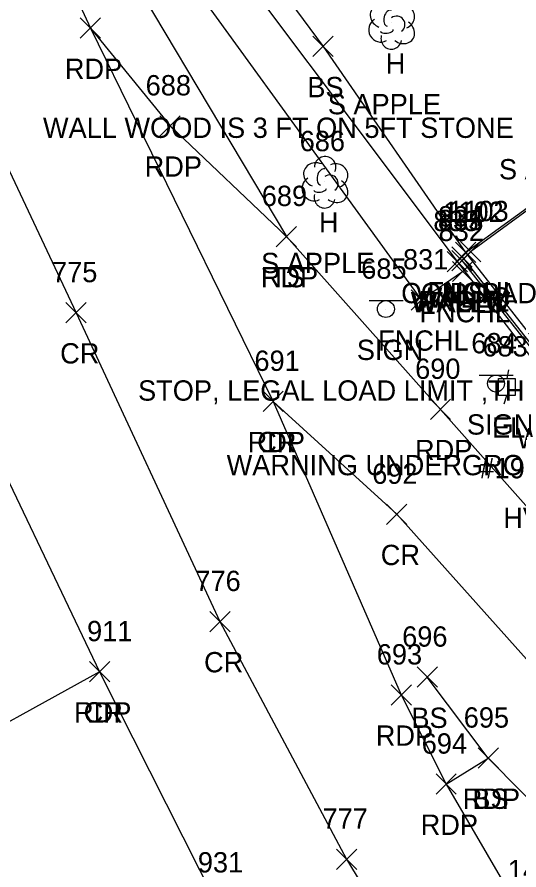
# Model space of a CAD drawing. Extents: x 1647133 to 1649138, y 411736 to 414924.
# Drawn here: x 1648639.6 to 1648689, y 412109.7 to 412193.6 of the extents above; entities that cross this region are included whole.
import ezdxf

# ---------------------------------------------------------------- set-up
doc = ezdxf.new("R2010")
doc.units = 0
for name, color, linetype in [('C_A', 7, 'Continuous'), ('L_A', 7, 'Continuous'), ('L_C', 7, 'Continuous'), ('L_I', 7, 'Continuous'), ('L_TIC', 7, 'Continuous'), ('LELB', 7, 'Continuous'), ('LFNC', 7, 'Continuous'), ('LS', 7, 'Continuous'), ('LTD', 7, 'Continuous'), ('LW', 7, 'Continuous'), ('P_A', 7, 'Continuous'), ('P_I', 7, 'Continuous'), ('P_TIC', 7, 'Continuous'), ('PET', 7, 'Continuous'), ('PRC', 7, 'Continuous'), ('R_I', 7, 'Continuous'), ('S_A', 7, 'Continuous'), ('S_C', 7, 'Continuous'), ('S_I', 7, 'Continuous'), ('SSGN', 7, 'Continuous'), ('U_A', 7, 'Continuous'), ('U_C', 7, 'Continuous'), ('U_I', 7, 'Continuous'), ('UEPT', 7, 'Continuous')]:
    doc.layers.add(name, color=color, linetype=linetype)

msp = doc.modelspace()

# ---------------------------------------------------------------- linework, layer by layer
at = {"layer": 'L_TIC'}
for points in [[(1648668.737, 412189.746), (1648670.737, 412191.746)], [(1648670.737, 412189.746), (1648668.737, 412191.746)], [(1648665.114, 412171.04), (1648667.114, 412173.04)], [(1648667.114, 412171.04), (1648665.114, 412173.04)], [(1648682.426, 412169.034), (1648684.426, 412171.034)], [(1648684.426, 412169.034), (1648682.426, 412171.034)], [(1648682.773, 412169.473), (1648684.773, 412171.473)], [(1648684.773, 412169.473), (1648682.773, 412171.473)], [(1648682.773, 412169.473), (1648684.773, 412171.473)], [(1648684.773, 412169.473), (1648682.773, 412171.473)], [(1648683.265, 412169.553), (1648685.265, 412171.553)], [(1648685.265, 412169.553), (1648683.265, 412171.553)], [(1648681.946, 412168.571), (1648683.946, 412170.571)], [(1648683.946, 412168.571), (1648681.946, 412170.571)], [(1648681.946, 412168.571), (1648683.946, 412170.571)], [(1648683.946, 412168.571), (1648681.946, 412170.571)], [(1648681.946, 412168.571), (1648683.946, 412170.571)], [(1648683.946, 412168.571), (1648681.946, 412170.571)], [(1648682.402, 412168.663), (1648684.402, 412170.663)], [(1648684.402, 412168.663), (1648682.402, 412170.663)], [(1648682.471, 412167.596), (1648684.471, 412169.596)], [(1648684.471, 412167.596), (1648682.471, 412169.596)], [(1648678.397, 412164.798), (1648680.397, 412166.798)], [(1648680.397, 412164.798), (1648678.397, 412166.798)], [(1648678.987, 412127.668), (1648680.987, 412129.668)], [(1648680.987, 412127.668), (1648678.987, 412129.668)], [(1648684.993, 412119.699), (1648686.993, 412121.699)], [(1648686.993, 412119.699), (1648684.993, 412121.699)]]:
    msp.add_lwpolyline(points, dxfattribs=at)
at = {"layer": 'LELB'}
for points in [[(1648569.547, 412372.007), (1648582.324, 412342.107), (1648598.266, 412308.648), (1648609.531, 412282.347), (1648621.029, 412259.099), (1648624.781, 412251.326), (1648635.367, 412226.993), (1648645.42, 412206.793), (1648666.114, 412172.04)], [(1648623.835, 412258.098), (1648637.368, 412228.397), (1648652.141, 412210.937), (1648646.596, 412221.306), (1648628.763, 412254.382), (1648641.62, 412261.648), (1648650.774, 412266.813), (1648653.575, 412263.089), (1648676.806, 412228.616), (1648679.956, 412223.635), (1648670.57, 412217.924), (1648655.389, 412210.124), (1648669.737, 412190.746), (1648683.773, 412170.473), (1648710.631, 412136.174)], [(1648685.993, 412120.699), (1648679.987, 412128.668)]]:
    msp.add_lwpolyline(points, dxfattribs=at)
at = {"layer": 'LFNC'}
for points in [[(1648652.618, 412210.345), (1648648.634, 412208.217), (1648679.397, 412165.798), (1648683.471, 412168.596)], [(1648684.265, 412170.553), (1648704.391, 412185.254), (1648720.455, 412164.525), (1648739.792, 412139.413), (1648738.276, 412138.056), (1648736.265, 412136.349), (1648725.233, 412127.52), (1648716.272, 412129.583)], [(1648683.402, 412169.663), (1648709.699, 412136.366)]]:
    msp.add_lwpolyline(points, dxfattribs=at)
at = {"layer": 'LS'}
msp.add_lwpolyline([(1648683.773, 412170.473), (1648704.589, 412185.571), (1648720.677, 412164.751), (1648740.213, 412139.354), (1648738.365, 412137.966), (1648738.276, 412138.056)], dxfattribs=at)
at = {"layer": 'LTD'}
for p, q in [((1648676.464, 412193.07), (1648676.464, 412193.07)), ((1648676.464, 412193.07), (1648676.464, 412193.07)), ((1648669.894, 412177.436), (1648669.894, 412177.436)), ((1648669.894, 412177.436), (1648669.894, 412177.436))]:
    msp.add_line(p, q, dxfattribs=at)
msp.add_arc((1648669.941, 412178.87), 1.047, 335.52715, 180.95627, dxfattribs=at)
for centre, major_axis, ratio, start_param, end_param in [((1648675.672, 412193.737), (1.21, -0.512), 0.895232, 1.570796, 4.712389), ((1648676.255, 412193.529), (-0.208, -0.792), 0.645439, 3.141593, 6.283185), ((1648677.505, 412193.654), (-1.141, -0.483), 0.949671, 1.570796, 4.712389), ((1648676.964, 412192.904), (-0.5, 0.667), 0.989748, 3.141593, 6.283185), ((1648675.381, 412192.362), (0.584, -1.042), 0.959034, 3.141593, 6.283185), ((1648677.464, 412192.237), (-1.09, 0.792), 0.841452, 1.570796, 4.712389), ((1648676.464, 412191.57), (0.265, 1.061), 0.942809, 1.570796, 4.712389), ((1648676.006, 412192.32), (-0.625, -0.083), 0.423636, 0, 3.141593), ((1648669.103, 412178.102), (1.21, -0.512), 0.895232, 1.570796, 4.712389), ((1648670.936, 412178.019), (-1.141, -0.483), 0.949671, 1.570796, 4.712389), ((1648669.686, 412177.894), (-0.208, -0.792), 0.645439, 3.141593, 6.283185), ((1648668.811, 412176.727), (0.584, -1.042), 0.959034, 3.141593, 6.283185), ((1648670.394, 412177.269), (-0.5, 0.667), 0.989748, 3.141593, 6.283185), ((1648670.895, 412176.602), (-1.09, 0.792), 0.841452, 1.570796, 4.712389), ((1648669.436, 412176.685), (-0.625, -0.083), 0.423636, 0, 3.141593), ((1648669.895, 412175.936), (0.265, 1.061), 0.942809, 1.570796, 4.712389)]:
    msp.add_ellipse(centre, major_axis=major_axis, ratio=ratio, start_param=start_param, end_param=end_param, dxfattribs=at)
at = {"layer": 'LW'}
for points in [[(1648653.627, 412208.663), (1648682.946, 412169.571)], [(1648682.946, 412169.571), (1648683.426, 412170.034), (1648710.056, 412136.22)], [(1648682.946, 412169.571), (1648693.247, 412156.182), (1648709.59, 412135.839), (1648710.056, 412136.22)]]:
    msp.add_lwpolyline(points, dxfattribs=at)
at = {"layer": 'P_TIC'}
for points in [[(1648645.814, 412191.55), (1648647.814, 412193.55)], [(1648647.814, 412191.55), (1648645.814, 412193.55)], [(1648645.814, 412191.55), (1648647.814, 412193.55)], [(1648647.814, 412191.55), (1648645.814, 412193.55)], [(1648653.671, 412181.929), (1648655.671, 412183.929)], [(1648655.671, 412181.929), (1648653.671, 412183.929)], [(1648665.114, 412171.04), (1648667.114, 412173.04)], [(1648667.114, 412171.04), (1648665.114, 412173.04)], [(1648644.407, 412163.541), (1648646.407, 412165.541)], [(1648646.407, 412163.541), (1648644.407, 412165.541)], [(1648663.816, 412154.812), (1648665.816, 412156.812)], [(1648665.816, 412154.812), (1648663.816, 412156.812)], [(1648663.816, 412154.812), (1648665.816, 412156.812)], [(1648665.816, 412154.812), (1648663.816, 412156.812)], [(1648680.295, 412154.026), (1648682.295, 412156.026)], [(1648682.295, 412154.026), (1648680.295, 412156.026)], [(1648675.979, 412143.697), (1648677.979, 412145.697)], [(1648677.979, 412143.697), (1648675.979, 412145.697)], [(1648658.578, 412133.14), (1648660.578, 412135.14)], [(1648660.578, 412133.14), (1648658.578, 412135.14)], [(1648646.722, 412128.202), (1648648.722, 412130.202)], [(1648648.722, 412128.202), (1648646.722, 412130.202)], [(1648646.722, 412128.202), (1648648.722, 412130.202)], [(1648648.722, 412128.202), (1648646.722, 412130.202)], [(1648676.431, 412125.914), (1648678.431, 412127.914)], [(1648678.431, 412125.914), (1648676.431, 412127.914)], [(1648684.993, 412119.699), (1648686.993, 412121.699)], [(1648686.993, 412119.699), (1648684.993, 412121.699)], [(1648680.854, 412117.139), (1648682.854, 412119.139)], [(1648682.854, 412117.139), (1648680.854, 412119.139)], [(1648680.854, 412117.139), (1648682.854, 412119.139)], [(1648682.854, 412117.139), (1648680.854, 412119.139)], [(1648671.041, 412109.748), (1648673.041, 412111.748)], [(1648673.041, 412109.748), (1648671.041, 412111.748)]]:
    msp.add_lwpolyline(points, dxfattribs=at)
at = {"layer": 'PET'}
for points in [[(1648536.119, 412432.998), (1648543.399, 412417.954), (1648546.486, 412415.003), (1648562.248, 412380.849), (1648562.337, 412375.739), (1648565.289, 412369.171), (1648579.297, 412340.19), (1648594.414, 412306.778), (1648606.351, 412280.635), (1648620.629, 412249.259), (1648631.777, 412225.06), (1648641.267, 412204.566), (1648646.814, 412192.55), (1648664.816, 412155.812), (1648677.431, 412126.914), (1648681.854, 412118.139), (1648693.972, 412097.362), (1648709.507, 412075.411), (1648723.887, 412057.125), (1648746.982, 412031.15), (1648768.696, 412011.078), (1648794.521, 411987.621), (1648826.406, 411959.789)], [(1648512.544, 412422.792), (1648530.09, 412384.206), (1648549.578, 412341.858), (1648567.717, 412302.186), (1648584.888, 412264.911), (1648603.961, 412222.556), (1648616.989, 412192.513), (1648626.592, 412174.015), (1648634.702, 412156.346), (1648647.722, 412129.202), (1648659.195, 412106.441), (1648667.013, 412092.615), (1648674.657, 412079.411), (1648685.658, 412062.516), (1648700.073, 412044.859), (1648717.467, 412025.769), (1648741.246, 412001.123), (1648755.318, 411988.116), (1648772.85, 411971.957)], [(1648646.814, 412192.55), (1648654.671, 412182.929), (1648666.114, 412172.04), (1648681.295, 412155.026), (1648700.204, 412133.762), (1648713.219, 412118.744), (1648733.101, 412096.235), (1648743.955, 412085.872), (1648754.321, 412079.376), (1648767.034, 412074.054), (1648779.661, 412072.471), (1648787.719, 412072.973), (1648803.342, 412081.153)], [(1648681.854, 412118.139), (1648685.993, 412120.699), (1648695.849, 412110.74)]]:
    msp.add_lwpolyline(points, dxfattribs=at)
at = {"layer": 'PRC'}
for points in [[(1648523.855, 412428.164), (1648541.762, 412388.819), (1648560.786, 412347.218), (1648578.952, 412307.656), (1648596.522, 412268.849), (1648615.514, 412228.06), (1648629.383, 412198.525), (1648645.407, 412164.541), (1648659.578, 412134.14), (1648672.041, 412110.748), (1648683.898, 412091.11), (1648700.383, 412068.335), (1648715.839, 412049.98), (1648739.601, 412024.905), (1648761.868, 412004.355), (1648787.636, 411981.064), (1648820.993, 411950.624), (1648837.381, 411936.249), (1648865.129, 411910.894), (1648893.845, 411885.618), (1648930.35, 411852.903), (1648951.421, 411834.103), (1648988.1, 411800.425), (1649025.041, 411766.663)], [(1648664.816, 412155.812), (1648676.979, 412144.697), (1648692.804, 412127.015), (1648705.779, 412111.7), (1648725.575, 412089.279), (1648736.199, 412077.337), (1648750.767, 412061.914), (1648770.244, 412040.325), (1648787.372, 412023.03), (1648802.926, 412006.988), (1648820.913, 411988.588), (1648839.835, 411968.01), (1648856.098, 411949.207), (1648864.815, 411933.931), (1648873.225, 411921.132)], [(1648647.722, 412129.202), (1648631.056, 412119.991), (1648616.796, 412112.345)]]:
    msp.add_lwpolyline(points, dxfattribs=at)
at = {"layer": 'SSGN'}
for p, q in [((1648674.271, 412165.736), (1648677.604, 412165.736)), ((1648675.918, 412164.903), (1648675.918, 412164.903)), ((1648685.114, 412158.395), (1648688.447, 412158.395)), ((1648686.761, 412157.562), (1648686.761, 412157.562))]:
    msp.add_line(p, q, dxfattribs=at)
for centre in [(1648675.918, 412164.903), (1648686.761, 412157.562)]:
    msp.add_circle(centre, 0.833, dxfattribs=at)
at = {"layer": 'UEPT'}
for p, q in [((1648687.996, 412158.901), (1648687.83, 412158.067)), ((1648686.996, 412156.401), (1648686.996, 412158.067)), ((1648686.996, 412158.067), (1648688.663, 412158.067)), ((1648688.663, 412158.067), (1648688.663, 412156.401)), ((1648687.83, 412157.234), (1648687.83, 412157.234)), ((1648688.663, 412156.401), (1648686.996, 412156.401)), ((1648687.58, 412155.567), (1648687.83, 412156.401))]:
    msp.add_line(p, q, dxfattribs=at)

# ---------------------------------------------------------------- texts
at = {"layer": 'C_A'}
msp.add_text('HVCTRL', height=2, dxfattribs=at).set_placement((1648687.477, 412143.341))
at = {"layer": 'L_A'}
for s, p in [('H', (1648675.897, 412188.07)), ('BS', (1648668.178, 412185.746)), ('H', (1648669.327, 412172.436)), ('TS', (1648664.524, 412167.04)), ('CONCPAD', (1648677.419, 412165.473)), ('FNCHL', (1648680.013, 412165.553)), ('BS', (1648682.214, 412165.473)), ('WALLW', (1648678.363, 412164.571)), ('WALLC', (1648678.482, 412164.571)), ('WALLC', (1648678.482, 412164.571)), ('WALLC', (1648678.962, 412165.034)), ('FNCHL', (1648679.15, 412164.663)), ('FNCHL', (1648679.219, 412163.596)), ('FNCHL', (1648675.145, 412160.798)), ('WALLC', (1648688.783, 412151.182)), ('BS', (1648678.428, 412123.668)), ('BS', (1648684.434, 412115.699))]:
    msp.add_text(s, height=2, dxfattribs=at).set_placement(p)
at = {"layer": 'L_C'}
for s, p in [('S APPLE', (1648670.196, 412184.07)), ('WALL WOOD IS 3 FT ON 5FT STONE', (1648642.147, 412181.746)), ('S APPLE', (1648687.055, 412177.664)), ('S APPLE', (1648663.627, 412168.436))]:
    msp.add_text(s, height=2, dxfattribs=at).set_placement(p)
at = {"layer": 'L_I'}
for s, p in [('686', (1648667.43, 412180.436)), ('689', (1648663.697, 412175.04)), ('834', (1648681.064, 412173.034)), ('1102', (1648681.569, 412173.473)), ('1102', (1648681.569, 412173.473)), ('1103', (1648682.06, 412173.553)), ('833', (1648680.584, 412172.571)), ('833', (1648680.584, 412172.571)), ('833', (1648680.584, 412172.571)), ('835', (1648681.04, 412172.663)), ('832', (1648681.109, 412171.596)), ('831', (1648677.602, 412168.798)), ('696', (1648677.522, 412131.668)), ('695', (1648683.584, 412123.699))]:
    msp.add_text(s, height=2, dxfattribs=at).set_placement(p)
at = {"layer": 'P_A'}
for s, p in [('RDP', (1648644.302, 412187.55)), ('RDP', (1648644.302, 412187.55)), ('RDP', (1648652.16, 412177.929)), ('RDP', (1648663.602, 412167.04)), ('CR', (1648643.84, 412159.541)), ('RDP', (1648662.304, 412150.812)), ('CR', (1648663.249, 412150.812)), ('RDP', (1648678.784, 412150.026)), ('CR', (1648675.412, 412139.697)), ('CR', (1648658.011, 412129.14)), ('RDP', (1648645.21, 412124.202)), ('CR', (1648646.155, 412124.202)), ('RDP', (1648674.919, 412121.914)), ('RDP', (1648683.481, 412115.699)), ('RDP', (1648679.342, 412113.139)), ('RDP', (1648679.342, 412113.139))]:
    msp.add_text(s, height=2, dxfattribs=at).set_placement(p)
at = {"layer": 'P_I'}
for s, p in [('688', (1648652.262, 412185.929)), ('689', (1648663.697, 412175.04)), ('775', (1648643.044, 412167.541)), ('691', (1648662.973, 412158.812)), ('691', (1648662.973, 412158.812)), ('690', (1648678.799, 412158.026)), ('692', (1648674.57, 412147.697)), ('776', (1648657.16, 412137.14)), ('911', (1648646.493, 412132.202)), ('911', (1648646.493, 412132.202)), ('693', (1648675.021, 412129.914)), ('695', (1648683.584, 412123.699)), ('694', (1648679.444, 412121.139)), ('694', (1648679.444, 412121.139)), ('777', (1648669.679, 412113.748)), ('931', (1648657.4, 412109.441))]:
    msp.add_text(s, height=2, dxfattribs=at).set_placement(p)
at = {"layer": 'R_I'}
msp.add_text('1414', height=2, dxfattribs=at).set_placement((1648687.928, 412108.682))
at = {"layer": 'S_A'}
for p in [(1648673.056, 412159.883), (1648683.899, 412152.541)]:
    msp.add_text('SIGN', height=2, dxfattribs=at).set_placement(p)
at = {"layer": 'S_C'}
for s, p in [('STOP, LEGAL LOAD LIMIT ,TH 89', (1648651.512, 412155.883)), ('WARNING UNDERGROUND TELEPHONE', (1648660.237, 412148.541))]:
    msp.add_text(s, height=2, dxfattribs=at).set_placement(p)
at = {"layer": 'S_I'}
for s, p in [('685', (1648673.489, 412167.883)), ('684', (1648684.332, 412160.541))]:
    msp.add_text(s, height=2, dxfattribs=at).set_placement(p)
at = {"layer": 'U_A'}
msp.add_text('EL', height=2, dxfattribs=at).set_placement((1648686.365, 412152.234))
at = {"layer": 'U_C'}
msp.add_text('#192', height=2, dxfattribs=at).set_placement((1648685.137, 412148.234))
at = {"layer": 'U_I'}
msp.add_text('683', height=2, dxfattribs=at).set_placement((1648685.42, 412160.234))

doc.saveas('drawing.dxf')
